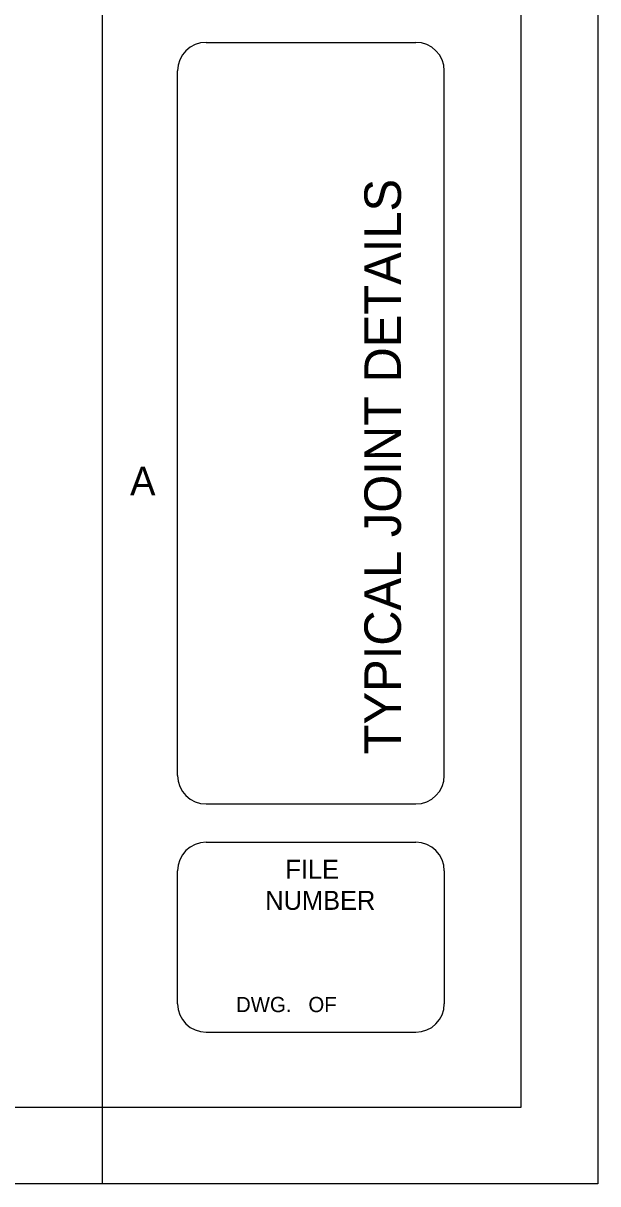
# Model space of a CAD drawing. Extents: x 44743.44 to 44747.1, y 44738.46 to 44741.29.
# Drawn here: x 44746.79 to 44747.105, y 44738.458 to 44739.093 of the extents above; entities that cross this region are included whole.
import ezdxf

# ---------------------------------------------------------------- set-up
doc = ezdxf.new("R2010")
doc.units = 0
for name, color, linetype in [('Level 1', 7, 'Continuous'), ('Level 10', 7, 'Continuous'), ('Level 2', 7, 'Continuous'), ('Level 3', 7, 'Continuous'), ('Level 9', 7, 'Continuous')]:
    doc.layers.add(name, color=color, linetype=linetype)

msp = doc.modelspace()

# ---------------------------------------------------------------- linework, layer by layer
at = {"layer": 'Level 1'}
for p, q in [((44746.89037, 44738.66583), (44747.00512, 44738.66583)), ((44746.89037, 44738.64483), (44747.00512, 44738.64483)), ((44746.89037, 44738.54083), (44747.00512, 44738.54083)), ((44746.80774, 44738.49983), (44746.84974, 44738.49983))]:
    msp.add_line(p, q, dxfattribs=at)
msp.add_lwpolyline([(44743.43805, 44741.29183), (44747.10474, 44741.29183), (44747.10474, 44738.45783), (44743.43805, 44738.45783)], close=True, dxfattribs=at)
for points in [[(44746.89037, 44739.08283), (44747.00512, 44739.08283)], [(44746.87474, 44738.68145), (44746.87474, 44739.0672)], [(44747.02074, 44738.68145), (44747.02074, 44739.0672)], [(44746.87474, 44738.55645), (44746.87474, 44738.6292)], [(44747.02074, 44738.6292), (44747.02074, 44738.55645)]]:
    msp.add_lwpolyline(points, dxfattribs=at)
for centre, radius, start, end in [((44746.89037, 44739.0672), 0.01563, 90, 180), ((44747.00512, 44739.0672), 0.01563, 0, 90), ((44746.89037, 44738.68145), 0.01563, 180, 270), ((44747.00512, 44738.68145), 0.01562, 270, 0), ((44746.89037, 44738.6292), 0.01562, 90, 180), ((44747.00512, 44738.6292), 0.01563, 0, 90), ((44746.89037, 44738.55645), 0.01563, 180, 270), ((44747.00512, 44738.55645), 0.01562, 270, 0)]:
    msp.add_arc(centre, radius, start, end, dxfattribs=at)
at = {"layer": 'Level 10'}
msp.add_line((44746.83374, 44738.45783), (44746.83374, 44738.49983), dxfattribs=at)
at = {"layer": 'Level 9'}
for p, q in [((44747.06274, 44738.49983), (44747.06274, 44741.24983)), ((44743.56305, 44738.49983), (44746.83374, 44738.49983)), ((44746.83374, 44738.49983), (44747.06274, 44738.49983))]:
    msp.add_line(p, q, dxfattribs=at)
msp.add_lwpolyline([(44746.83374, 44738.49983), (44746.83374, 44741.24983)], dxfattribs=at)

# ---------------------------------------------------------------- texts
at = {"layer": 'Level 1'}
msp.add_text('A', height=0.01561, dxfattribs=at).set_placement((44746.84874, 44738.83483))
at = {"layer": 'Level 2'}
for s, height, p in [('FILE', 0.010398, (44746.93374, 44738.62483)), ('NUMBER', 0.010398, (44746.92274, 44738.60783)), ('DWG.   OF  ', 0.008334, (44746.90674, 44738.55183))]:
    msp.add_text(s, height=height, dxfattribs=at).set_placement(p)
at = {"layer": 'Level 3'}
msp.add_text('TYPICAL JOINT DETAILS', height=0.0199998, rotation=90, dxfattribs=at).set_placement((44746.997, 44738.69301))

doc.saveas('drawing.dxf')
